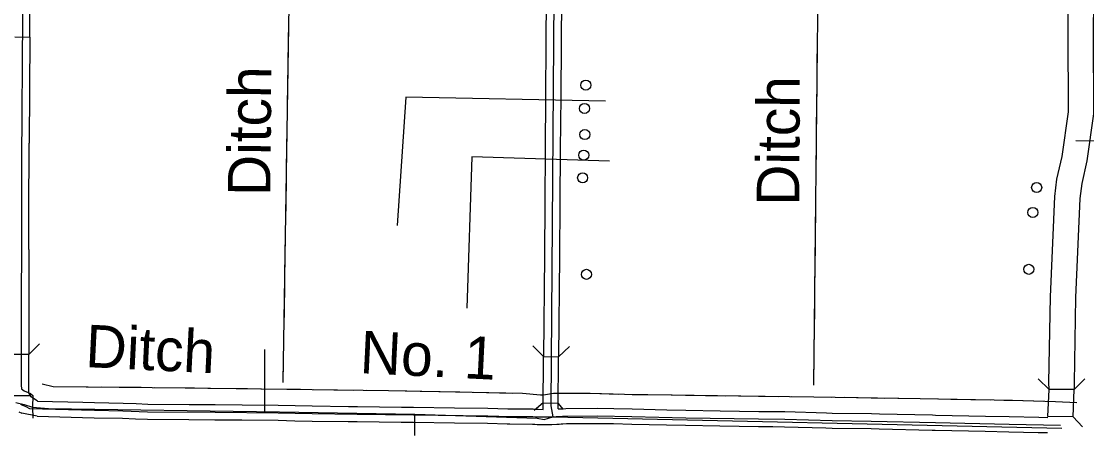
# Model space of a CAD drawing. Extents: x -4306 to 3843, y 131 to 8341.
# Drawn here: x -1949 to -255, y 221 to 879 of the extents above; entities that cross this region are included whole.
import ezdxf

# ---------------------------------------------------------------- set-up
doc = ezdxf.new("R2010")
doc.units = 0
for name, color, linetype in [('10', 7, 'Continuous'), ('31', 7, 'Continuous'), ('32', 7, 'Continuous'), ('38', 7, 'Continuous'), ('55', 7, 'Continuous'), ('56', 7, 'Continuous'), ('57', 7, 'Continuous'), ('62', 7, 'Continuous')]:
    doc.layers.add(name, color=color, linetype=linetype)

msp = doc.modelspace()

# ---------------------------------------------------------------- linework, layer by layer
at = {"layer": '10'}
for p, q in [((-316.2, 250.9), (-314.4, 293.8)), ((-274.4, 294), (-314.4, 293.9)), ((-276.2, 250.6), (-274.4, 293.9)), ((-276.2, 250.6), (-316.2, 250.9))]:
    msp.add_line(p, q, dxfattribs=at)
for points in [[(-314.4, 293.8), (-314.5, 305.1), (-312.3, 441.3), (-305.4, 600.9), (-302, 628.3), (-293.8, 664.7), (-283.6, 735.2), (-284.1, 861.9), (-282.2, 1054.1), (-278.9, 1201.3), (-280.3, 1434.8), (-278.7, 1599.9), (-273.4, 1758.6), (-274.2, 1917.6), (-271, 2305.4), (-270.3, 2716.6), (-269.9, 2753.7)], [(-229.9, 2753.2), (-230.3, 2716.3), (-231, 2305.2), (-234.2, 1917.5), (-233.4, 1758), (-238.7, 1599), (-240.3, 1434.8), (-238.9, 1200.9), (-242.2, 1053.5), (-244.1, 861.8), (-243.5, 732.4), (-254.4, 657.4), (-262.5, 621.4), (-265.5, 597.6), (-272.4, 440.2), (-274.5, 304.9), (-274.4, 293.9)]]:
    msp.add_lwpolyline(points, dxfattribs=at)
at = {"layer": '31'}
for p, q in [((-1959.7, 854.5), (-1935.7, 854.4)), ((-1935.7, 854.4), (-1936.3, 769.9)), ((-1936.3, 769.9), (-1936.9, 685.4)), ((-1936.9, 685.4), (-1936.9, 685.4)), ((-1937.4, 516.5), (-1937.5, 432)), ((-1937.5, 432), (-1937.5, 349.7)), ((-1937.5, 349.7), (-1961.5, 349.7)), ((-1937.5, 342.7), (-1937.5, 349.7)), ((-1937.5, 341), (-1937.5, 342.7)), ((-1937.5, 302), (-1937.5, 341)), ((-1937.3, 289), (-1937.5, 302)), ((-1933.7, 282.5), (-1937.3, 289)), ((-1934.5, 283.9), (-1961.5, 284)), ((-1923.6, 275.5), (-1933.7, 282.5))]:
    msp.add_line(p, q, dxfattribs=at)
for points in [[(-1935.7, 854.4), (-1935.1, 938.9)], [(-1937.2, 601), (-1937.1, 657.8), (-1936.9, 685.4)], [(-1937.4, 516.5), (-1937.2, 601)]]:
    msp.add_lwpolyline(points, dxfattribs=at)
at = {"layer": '32'}
for p, q in [((-1100.7, 1107.1), (-1107, 268.2)), ((-1114.1, 928.8), (-1114.7, 844.4)), ((-1090.1, 928.7), (-1090.7, 844.2)), ((-1114.7, 844.4), (-1115.3, 759.9)), ((-1090.7, 844.2), (-1091.3, 759.7)), ((-1115.3, 759.9), (-1116, 675.4)), ((-1091.3, 759.7), (-1092, 675.2)), ((-1116, 675.4), (-1116.6, 590.9)), ((-1092, 675.2), (-1092.6, 590.7)), ((-1116.6, 590.9), (-1117.2, 506.4)), ((-1092.6, 590.7), (-1093.2, 506.2)), ((-1117.2, 506.4), (-1118.7, 346.4)), ((-1093.2, 506.2), (-1094.7, 345.8)), ((-1562.5, 357.5), (-1562.4, 258.6)), ((-1119.3, 262.4), (-1118.7, 346.4)), ((-1118.7, 346.4), (-1094.7, 345.8)), ((-1095.3, 263.1), (-1094.7, 345.8)), ((-1958.3, 273.4), (-1944.6, 270.2)), ((-1923.6, 275.5), (-1851.4, 273.7)), ((-1851.4, 273.7), (-1832.8, 273.2)), ((-1832.8, 273.2), (-1787.5, 272.4)), ((-1787.5, 272.4), (-1766.7, 271.6)), ((-1766.7, 271.6), (-1748.2, 270.8)), ((-1119.2, 273.1), (-1095.2, 272.5)), ((-1953.5, 258.8), (-1948.3, 256.3)), ((-1950.7, 270.6), (-1948.8, 269.9)), ((-1948.8, 269.9), (-1944.7, 267.9)), ((-1924.4, 251.5), (-1948.3, 256.3)), ((-1944.7, 267.9), (-1942.2, 266.8)), ((-1944.6, 270.2), (-1931.4, 265.8)), ((-1942.2, 266.8), (-1936.1, 263.8)), ((-1936.1, 263.8), (-1833, 261.2)), ((-1931.4, 265.8), (-1905.9, 264)), ((-1905.9, 264), (-1538.4, 258.6)), ((-1833, 261.2), (-1787.9, 260.4)), ((-1787.9, 260.4), (-1748.4, 258.8)), ((-1748.4, 258.8), (-1641.2, 258)), ((-1748.2, 270.8), (-1682.6, 270.3)), ((-1682.6, 270.3), (-1641.1, 270)), ((-1641.2, 258), (-1540.8, 257.1)), ((-1641.1, 270), (-1598.1, 269.6)), ((-1598.1, 269.6), (-1540.7, 269.1)), ((-1540.8, 257.1), (-1486.7, 255.9)), ((-1540.7, 269.1), (-1513.5, 268.5)), ((-1538.4, 258.6), (-1323.2, 254.6)), ((-1513.5, 268.5), (-1486.5, 267.9)), ((-1486.7, 255.9), (-1414.9, 255)), ((-1486.5, 267.9), (-1429.1, 267.1)), ((-1429.1, 267.1), (-1414.8, 267)), ((-1414.9, 255), (-1325.5, 254)), ((-1414.8, 267), (-1344.7, 266.2)), ((-1344.7, 266.2), (-1325.3, 266)), ((-1325.3, 266), (-1260.2, 265.1)), ((-1323.3, 220.7), (-1323.2, 254.6)), ((-1323.2, 254.6), (-1128.7, 248.6)), ((-1260.2, 265.1), (-1207, 264.4)), ((-1207, 264.4), (-1175.5, 263.4)), ((-1175.5, 263.4), (-1171.6, 263.3)), ((-1171.6, 263.3), (-1135.1, 263.2)), ((-1135.1, 263.2), (-1130.4, 262.8)), ((-1130.4, 262.8), (-1127.4, 262.6)), ((-1127.4, 262.6), (-1119.3, 262.4)), ((-1107, 268.2), (-1103.8, 250.6)), ((-1095.3, 263.1), (-1092.1, 263.3)), ((-1092.1, 263.3), (-1089.4, 263.4)), ((-1089.4, 263.4), (-1083.2, 263.9)), ((-1083.2, 263.9), (-1032.4, 264.2)), ((-1032.4, 264.2), (-1006.7, 263.8)), ((-1006.7, 263.8), (-977.7, 263.2)), ((-977.7, 263.2), (-922.2, 261.9)), ((-922.2, 261.9), (-892.2, 261.2)), ((-892.2, 261.2), (-837.8, 260.3)), ((-837.8, 260.3), (-776.3, 259.3)), ((-776.3, 259.3), (-753.4, 259.1)), ((-753.4, 259.1), (-734.7, 258.9)), ((-734.7, 258.9), (-668.7, 257)), ((-668.7, 257), (-659.2, 256.7)), ((-659.2, 256.7), (-597, 255.8)), ((-597, 255.8), (-584.3, 255.5)), ((-584.3, 255.5), (-499.8, 253.6)), ((-1924.4, 251.5), (-1852, 249.7)), ((-1852, 249.7), (-1833.3, 249.2)), ((-1833.3, 249.2), (-1788.2, 248.4)), ((-1788.2, 248.4), (-1767.7, 247.6)), ((-1767.7, 247.6), (-1748.7, 246.8)), ((-1748.7, 246.8), (-1682.8, 246.3)), ((-1682.8, 246.3), (-1641.3, 246)), ((-1641.3, 246), (-1598.3, 245.6)), ((-1598.3, 245.6), (-1541, 245.1)), ((-1541, 245.1), (-1514, 244.5)), ((-1514, 244.5), (-1486.9, 243.9)), ((-1486.9, 243.9), (-1429.4, 243.1)), ((-1429.4, 243.1), (-1415.1, 243)), ((-1415.1, 243), (-1344.9, 242.2)), ((-1344.9, 242.2), (-1325.6, 242)), ((-1325.6, 242), (-1260.5, 241.1)), ((-1325.5, 254), (-1207.3, 252.4)), ((-1260.5, 241.1), (-1207.6, 240.4)), ((-1207.6, 240.4), (-1176.2, 239.4)), ((-1207.3, 252.4), (-1171.8, 251.3)), ((-1176.2, 239.4), (-1172, 239.3)), ((-1172, 239.3), (-1136.2, 239.2)), ((-1171.8, 251.3), (-1135.6, 251.2)), ((-1136.2, 239.2), (-1132.4, 238.9)), ((-1135.6, 251.2), (-1131.4, 250.8)), ((-1132.4, 238.9), (-1128.6, 238.6)), ((-1131.4, 250.8), (-1128, 250.6)), ((-1128.7, 248.6), (-1117.8, 246.4)), ((-1128.6, 238.6), (-1121.9, 238.5)), ((-1128, 250.6), (-1121.8, 250.5)), ((-1121.9, 238.5), (-1110, 238.5)), ((-1121.8, 250.5), (-1110.2, 250.5)), ((-1117.8, 246.4), (-1103.8, 250.6)), ((-1110.2, 250.5), (-1105.9, 250.6)), ((-1110, 238.5), (-1105.6, 238.6)), ((-1105.9, 250.6), (-1098.3, 250.9)), ((-1105.6, 238.6), (-1097.7, 238.9)), ((-1103.8, 250.6), (-294.3, 232.4)), ((-1098.3, 250.9), (-1094.4, 251.1)), ((-1097.7, 238.9), (-1093.6, 239.2)), ((-1094.4, 251.1), (-1088.6, 251.5)), ((-1093.6, 239.2), (-1090.7, 239.3)), ((-1090.7, 239.3), (-1087.8, 239.5)), ((-1088.6, 251.5), (-1082.7, 251.9)), ((-1087.8, 239.5), (-1082.2, 239.9)), ((-1082.7, 251.9), (-1032.5, 252.2)), ((-1082.2, 239.9), (-1032.6, 240.2)), ((-1032.6, 240.2), (-1007.2, 239.8)), ((-1032.5, 252.2), (-978, 251.2)), ((-1007.2, 239.8), (-978.2, 239.2)), ((-978.2, 239.2), (-922.8, 237.9)), ((-978, 251.2), (-892.4, 249.2)), ((-922.8, 237.9), (-892.7, 237.2)), ((-892.4, 249.2), (-776.5, 247.3)), ((-776.5, 247.3), (-735, 246.9)), ((-735, 246.9), (-659.4, 244.7)), ((-659.4, 244.7), (-597.3, 243.8)), ((-597.3, 243.8), (-495.1, 241.5)), ((-499.8, 253.6), (-494.8, 253.5)), ((-495.1, 241.5), (-378, 239)), ((-494.8, 253.5), (-415.4, 251.8)), ((-415.4, 251.8), (-377.8, 251)), ((-378, 239), (-296.2, 237.1)), ((-377.8, 251), (-330.9, 249.9)), ((-330.9, 249.9), (-316.4, 249.5)), ((-892.7, 237.2), (-838.2, 236.3)), ((-838.2, 236.3), (-776.6, 235.3)), ((-776.6, 235.3), (-753.6, 235.1)), ((-753.6, 235.1), (-735.2, 234.9)), ((-735.2, 234.9), (-669.4, 233)), ((-669.4, 233), (-659.7, 232.7)), ((-659.7, 232.7), (-597.5, 231.8)), ((-597.5, 231.8), (-584.9, 231.5)), ((-584.9, 231.5), (-500.4, 229.6)), ((-500.4, 229.6), (-495.4, 229.5)), ((-495.4, 229.5), (-415.9, 227.8)), ((-415.9, 227.8), (-378.3, 227)), ((-378.3, 227), (-331.5, 225.9)), ((-331.5, 225.9), (-316.8, 225.6))]:
    msp.add_line(p, q, dxfattribs=at)
for points in [[(-1927.2, 3133.3), (-1928.9, 2805.9), (-1937.5, 1957.3), (-1941.9, 1537.3), (-1945.9, 1118.2), (-1949.1, 657.8)], [(2052.2, 1131.5), (2052.1, 731.6), (2051.2, 728.2), (2048.7, 726.1), (1900.1, 653.4), (1410.3, 639.5), (1370.3, 641.2), (1252.7, 662.8), (1223, 668.4), (1168.4, 681.6), (1136.3, 683.4), (569.9, 686.2), (-271.6, 689.6)], [(-1949.1, 657.8), (-1949.8, 300.7), (-1949.1, 294.9), (-1944.6, 292.1), (-1938.5, 289.2), (-1934.7, 287.6), (-1930.8, 284.4), (-1931.4, 265.8), (-1931.3, 248.5)]]:
    msp.add_lwpolyline(points, dxfattribs=at)
at = {"layer": '38'}
for p, q in [((-1118.7, 346.4), (-1135.4, 363.6)), ((-1077.5, 362.6), (-1094.7, 345.8)), ((-1119.2, 273.1), (-1133.6, 260.9)), ((-1086.8, 262.4), (-1095.2, 272.5))]:
    msp.add_line(p, q, dxfattribs=at)
msp.add_lwpolyline([(-1920.5, 366.6), (-1937.5, 349.7)], dxfattribs=at)
at = {"layer": '55'}
for p, q in [((-1337.7, 758.7), (-1351.4, 554.6)), ((-1020, 752.3), (-1337.7, 758.7)), ((-1232.7, 663.9), (-1240.8, 423.1)), ((-1013.7, 656.9), (-1232.7, 663.9))]:
    msp.add_line(p, q, dxfattribs=at)
at = {"layer": '56'}
for points in [[(-1521.8, 1099.7), (-1522.9, 972), (-1533.2, 305.2)], [(-680.6, 1081.4), (-689.1, 300.9)], [(-1524.4, 877.9), (-1525.3, 814.6)], [(-683.1, 859.6), (-683.7, 796.3)], [(-1525.7, 793.5), (-1526.6, 730.1)], [(-684, 775.1), (-684.7, 711.8)], [(-1527, 709), (-1527.9, 645.6)], [(-684.9, 690.7), (-685.6, 627.3)], [(-1528.3, 624.5), (-1528.8, 592.8)], [(-685.8, 606.2), (-686.2, 574.5)], [(-1528.8, 592.8), (-1529.2, 561.1)], [(-686.2, 574.5), (-686.5, 542.8)], [(-1529.6, 540), (-1530.5, 476.7)], [(-686.7, 521.7), (-687.4, 458.3)], [(-1530.9, 455.5), (-1531.8, 392.2)], [(-687.6, 437.2), (-688.3, 373.8)], [(-1532.2, 371.1), (-1533.1, 307.7)], [(-688.6, 352.7), (-689.1, 300.9)], [(-1843, 297.9), (-1898.8, 298.5), (-1916.2, 302.8)], [(-270, 272.8), (-304.3, 274.6), (-372.7, 276.6), (-519.6, 279), (-688.7, 281.9), (-804.7, 283.2), (-989.8, 286), (-1044.3, 287.5), (-1103, 287.5), (-1118.4, 285), (-1123.6, 284.8), (-1151.9, 287.5), (-1365.2, 292), (-1688.9, 296.2), (-1898.8, 298.5)], [(-1790.2, 297.3), (-1821.9, 297.7)], [(-1758.5, 297), (-1790.2, 297.3)], [(-1674.1, 296), (-1688.9, 296.2), (-1737.4, 296.7)], [(-1589.6, 294.9), (-1652.9, 295.7)], [(-1505.1, 293.8), (-1568.5, 294.6)], [(-1420.6, 292.7), (-1484, 293.6)], [(-1336.1, 291.4), (-1365.2, 292), (-1399.5, 292.5)], [(-1283.3, 290.3), (-1315, 291)], [(-1251.7, 289.6), (-1283.3, 290.3)], [(-1167.2, 287.8), (-1230.6, 289.2)], [(-998.6, 286.2), (-1044.3, 287.5), (-1061.9, 287.5)], [(-914.1, 284.9), (-977.5, 285.8)], [(-829.6, 283.6), (-893, 284.6)], [(-776.8, 282.9), (-804.7, 283.2), (-808.5, 283.3)], [(-745.1, 282.6), (-776.8, 282.9)], [(-660.7, 281.4), (-688.7, 281.9), (-724, 282.3)], [(-576.2, 279.9), (-639.5, 281.1)], [(-491.7, 278.5), (-519.6, 279), (-555.1, 279.6)], [(-407.2, 277.1), (-470.6, 278.2)], [(-322.8, 275.2), (-372.7, 276.6), (-386.1, 276.8)]]:
    msp.add_lwpolyline(points, dxfattribs=at)
at = {"layer": '57'}
for centre in [(-1051.3, 778), (-1053.5, 740.9), (-1052.9, 699.3), (-1054.7, 666.6), (-1056.4, 630.6), (-334.1, 615.1), (-340.2, 575.6), (-346.7, 485.1), (-1050.4, 477.1)]:
    msp.add_circle(centre, 8, dxfattribs=at)
at = {"layer": '62'}
for p, q in [((-331.5, 310.8), (-314.4, 293.9)), ((-274.4, 294), (-257.5, 311.1)), ((-261.4, 234.8), (-276.2, 250.6))]:
    msp.add_line(p, q, dxfattribs=at)

# ---------------------------------------------------------------- texts
at = {"layer": '56'}
for s, rotation, p in [('Ditch', 89.5668, (-1553.2, 601.5)), ('Ditch', 89.7133, (-711.9, 586.1)), ('Ditch', 357.2006, (-1848.3, 329.8)), ('No. 1', 357.2006, (-1411.7, 320.1))]:
    msp.add_text(s, height=67.59, rotation=rotation, dxfattribs=at).set_placement(p)

doc.saveas('drawing.dxf')
